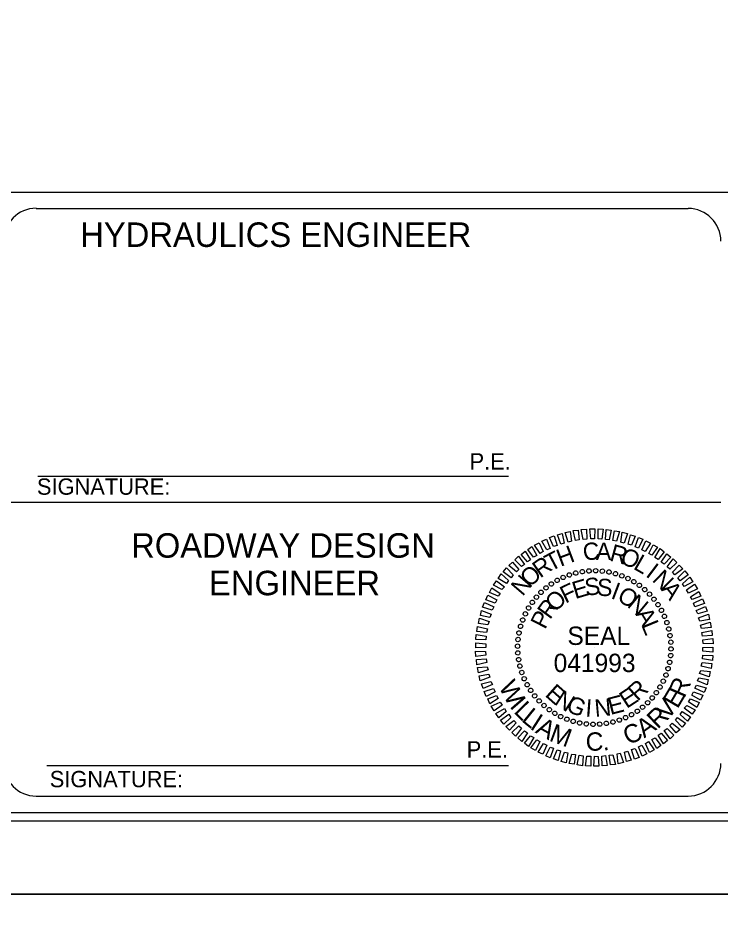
# Model space of a CAD drawing. Extents: x 925297 to 940193, y 663541 to 689899.
# Drawn here: x 935468 to 937191, y 681019 to 683245 of the extents above; entities that cross this region are included whole.
import ezdxf

# ---------------------------------------------------------------- set-up
doc = ezdxf.new("R2010")
doc.units = 0
for name, color, linetype in [('Default', 7, 'Continuous'), ('Sheet Cutting Line CELL', 7, 'Continuous'), ('Sheet Plot Border Inside CELL', 7, 'Continuous'), ('Sheet Plot Border Outside CELL', 7, 'Continuous'), ('Sheet Title CELL', 7, 'Continuous')]:
    doc.layers.add(name, color=color, linetype=linetype)

msp = doc.modelspace()

# ---------------------------------------------------------------- linework, layer by layer
at = {"layer": 'Default'}
for p, q in [((936819.3, 681881.1), (936819.3, 681881.1)), ((936835, 681885.6), (936835, 681885.6)), ((936851.5, 681888.6), (936851.5, 681888.6)), ((936867.6, 681890.9), (936867.6, 681890.9)), ((936884.1, 681891.3), (936884.1, 681891.3)), ((936900.6, 681890.1), (936900.6, 681890.1)), ((936916.8, 681887.5), (936916.8, 681887.5)), ((936932.5, 681884.1), (936932.5, 681884.1)), ((936775.4, 681859), (936775.4, 681859)), ((936789.6, 681867.6), (936789.6, 681867.6)), ((936804.3, 681875.1), (936804.3, 681875.1)), ((936948.3, 681878.9), (936948.3, 681878.9)), ((936963.3, 681872.1), (936963.3, 681872.1)), ((936977.9, 681864.6), (936977.9, 681864.6)), ((936749.9, 681838.4), (936749.9, 681838.4)), ((936762.3, 681849.6), (936762.3, 681849.6)), ((936991.4, 681855.3), (936991.4, 681855.3)), ((937004.5, 681845.1), (937004.5, 681845.1)), ((936728.5, 681813.6), (936728.5, 681813.6)), ((936738.6, 681826.8), (936738.6, 681826.8)), ((937016.1, 681833.9), (937016.1, 681833.9)), ((937027.4, 681821.5), (937027.4, 681821.5)), ((936719.1, 681800.1), (936719.1, 681800.1)), ((937036.8, 681808.4), (937036.8, 681808.4)), ((937045.4, 681794.1), (937045.4, 681794.1)), ((936704.9, 681770.5), (936704.9, 681770.5)), ((936711.6, 681785.5), (936711.6, 681785.5)), ((937052.9, 681779.5), (937052.9, 681779.5)), ((936699.6, 681754.8), (936699.6, 681754.8)), ((937058.9, 681764.5), (937058.9, 681764.5)), ((937063.4, 681748.8), (937063.4, 681748.8)), ((936696.3, 681739), (936696.3, 681739)), ((937066.4, 681732.3), (937066.4, 681732.3)), ((936692.5, 681706.4), (936692.5, 681706.4)), ((936693.6, 681722.9), (936693.6, 681722.9)), ((936880.8, 681703), (936880.8, 681703)), ((937068.6, 681716.1), (937068.6, 681716.1)), ((936692.9, 681689.9), (936692.9, 681689.9)), ((937067.9, 681683.1), (937067.9, 681683.1)), ((937069, 681699.6), (937069, 681699.6)), ((936695.1, 681673.8), (936695.1, 681673.8)), ((936698.1, 681657.3), (936698.1, 681657.3)), ((937065.3, 681667), (937065.3, 681667)), ((936702.6, 681641.5), (936702.6, 681641.5)), ((937056.6, 681635.5), (937056.6, 681635.5)), ((937061.9, 681651.3), (937061.9, 681651.3)), ((936708.6, 681626.5), (936708.6, 681626.5)), ((937049.9, 681620.5), (937049.9, 681620.5)), ((936716.1, 681611.9), (936716.1, 681611.9)), ((936724.8, 681597.6), (936724.8, 681597.6)), ((937033, 681592.4), (937033, 681592.4)), ((937042.4, 681605.9), (937042.4, 681605.9)), ((936734.1, 681584.5), (936734.1, 681584.5)), ((936745.4, 681572.1), (936745.4, 681572.1)), ((937011.6, 681567.6), (937011.6, 681567.6)), ((937022.9, 681579.3), (937022.9, 681579.3)), ((936757, 681560.9), (936757, 681560.9)), ((936770.1, 681550.8), (936770.1, 681550.8)), ((936986.1, 681547), (936986.1, 681547)), ((936999.3, 681556.4), (936999.3, 681556.4)), ((936783.6, 681541.4), (936783.6, 681541.4)), ((936798.3, 681533.9), (936798.3, 681533.9)), ((936813.3, 681527.1), (936813.3, 681527.1)), ((936942.3, 681524.9), (936942.3, 681524.9)), ((936957.3, 681530.9), (936957.3, 681530.9)), ((936971.9, 681538.4), (936971.9, 681538.4)), ((936829, 681521.9), (936829, 681521.9)), ((936844.8, 681518.5), (936844.8, 681518.5)), ((936860.9, 681515.9), (936860.9, 681515.9)), ((936877.4, 681514.8), (936877.4, 681514.8)), ((936893.9, 681515.1), (936893.9, 681515.1)), ((936910, 681517.4), (936910, 681517.4)), ((936926.5, 681520.4), (936926.5, 681520.4))]:
    msp.add_line(p, q, dxfattribs=at)
for points in [[(936835, 681965.5), (936829, 681989.5), (936841.4, 681990.6), (936844, 681966.6)], [(936853, 681967.8), (936848.9, 681991.8), (936861.6, 681993.3), (936862, 681968.9)], [(936871.8, 681969.6), (936869.9, 681994), (936882.3, 681993.6), (936880.8, 681969.3)], [(936889.8, 681969.3), (936889.8, 681993.6), (936902.1, 681993.3), (936898.8, 681968.9)], [(936908.5, 681968.1), (936910, 681992.5), (936922.4, 681990.3), (936917.5, 681966.6)], [(936764.1, 681942.6), (936752.1, 681963.6), (936763.8, 681968.9), (936772.4, 681946)], [(936780.6, 681950.5), (936770.9, 681972.3), (936782.1, 681976.8), (936790, 681952.8)], [(936799, 681956.5), (936790.4, 681979), (936802, 681982.4), (936806.9, 681959.1)], [(936817, 681961.4), (936809.1, 681985), (936821.9, 681987.6), (936824.9, 681963.3)], [(936926.5, 681965.1), (936929.9, 681989.1), (936942.3, 681987.3), (936935.5, 681964)], [(936945.6, 681961), (936949.4, 681985.4), (936962.1, 681982.4), (936953.5, 681959.1)], [(936963.6, 681956.1), (936969.3, 681979.4), (936980.9, 681975.6), (936971.5, 681953.5)], [(936980.5, 681949.4), (936989.1, 681973), (936999.6, 681968.5), (936989.1, 681946.8)], [(936731.5, 681924.3), (936717.6, 681943.4), (936727.4, 681950.5), (936739.8, 681928.8)], [(936748, 681933.6), (936734.1, 681953.9), (936745.8, 681959.9), (936755.1, 681938.1)], [(936997.4, 681942.3), (937006.8, 681964.4), (937018.4, 681959.1), (937005.6, 681938.1)], [(937014.6, 681933.6), (937024.8, 681955), (937036, 681948.6), (937021.8, 681929.1)], [(936702.3, 681901.4), (936685.8, 681917.9), (936694.8, 681926.9), (936709.4, 681906.6)], [(936717.3, 681913), (936701.1, 681931), (936711.3, 681938.9), (936724.4, 681917.9)], [(937029.3, 681923.5), (937042.4, 681945.3), (937052.1, 681937.4), (937037.5, 681919)], [(937044.6, 681912.3), (937058.5, 681932.9), (937068.3, 681924.6), (937051.8, 681907)], [(936689.9, 681888.3), (936670.8, 681903.6), (936680.1, 681912.3), (936695.9, 681894.3)], [(937058.9, 681900.6), (937074.3, 681920.1), (937083.3, 681911.1), (937066, 681895)], [(937072.4, 681887.5), (937088.5, 681905.1), (937097.5, 681896.1), (937078, 681881.5)], [(936665.5, 681859.8), (936645.3, 681872.5), (936652.4, 681883.4), (936670.4, 681866.9)], [(936676.8, 681874), (936657.3, 681888.6), (936665.5, 681898.4), (936682, 681880.8)], [(937085.5, 681874), (937102.8, 681890.9), (937110.6, 681880.8), (937090.8, 681866.5)], [(936654.3, 681844.8), (936633.3, 681856), (936640.8, 681866.5), (936660.3, 681851.5)], [(937096.8, 681859.4), (937115.1, 681875.1), (937122.3, 681864.3), (937101.3, 681852.3)], [(937106.5, 681844), (937126.4, 681858.3), (937133.5, 681847), (937111.8, 681836.5)], [(936645.3, 681828.6), (936623.9, 681838), (936629.5, 681849.6), (936649.8, 681835.8)], [(937116.3, 681827.5), (937137.3, 681840.6), (937142.1, 681829), (937120.8, 681820.4)], [(936630.3, 681794.9), (936607, 681801.6), (936611.9, 681813.3), (936634.4, 681802.8)], [(936637.8, 681811.4), (936614.5, 681820), (936620.1, 681831.6), (936641.5, 681819.6)], [(937123.8, 681811.4), (937145.9, 681822.6), (937150.8, 681810.6), (937127.5, 681803.1)], [(936624.6, 681776.9), (936601.4, 681781.8), (936604, 681794.1), (936627.6, 681784.8)], [(937130.5, 681793.8), (937153.4, 681803.5), (937157.5, 681791.9), (937134.3, 681785.9)], [(936619.8, 681758.9), (936596.5, 681761.9), (936599.1, 681774.6), (936622.8, 681766.8)], [(937136.5, 681775.8), (937160.5, 681784.4), (937162.8, 681772), (937139.1, 681767.9)], [(936616.8, 681739.8), (936592.8, 681742), (936594.3, 681754.8), (936618.6, 681748.8)], [(937141, 681757.8), (937164.6, 681764.9), (937166.9, 681752.1), (937143.3, 681749.9)], [(936614.9, 681721.8), (936590.5, 681722.5), (936591.3, 681734.9), (936615.6, 681730.8)], [(937144.4, 681739.8), (937168.8, 681745), (937169.9, 681732.3), (937145.9, 681730.8)], [(937146.6, 681721.8), (937171, 681724.8), (937171.8, 681712), (937147.4, 681712.8)], [(936614.5, 681703), (936590.1, 681701.9), (936590.1, 681714.6), (936614.5, 681712)], [(937147, 681703), (937171.4, 681704.1), (937171.4, 681691.4), (937147, 681694)], [(936614.9, 681684.3), (936590.5, 681681.3), (936589.8, 681694), (936614.1, 681693.3)], [(937146.6, 681684.3), (937171, 681683.5), (937170.3, 681671.1), (937145.9, 681675.3)], [(936617.1, 681666.3), (936592.8, 681661), (936591.6, 681673.8), (936615.6, 681675.3)], [(937144.8, 681666.3), (937168.8, 681664), (937167.3, 681651.3), (937142.9, 681657.3)], [(936620.5, 681648.3), (936596.9, 681641.1), (936594.6, 681653.9), (936618.3, 681656.1)], [(936625, 681630.3), (936601, 681621.6), (936598.8, 681634), (936622.4, 681638.1)], [(937141.8, 681647.1), (937165, 681644.1), (937162.4, 681631.4), (937138.8, 681639.3)], [(936631, 681612.3), (936608.1, 681602.5), (936604, 681614.1), (936627.3, 681620.1)], [(937136.9, 681629.1), (937160.1, 681624.3), (937157.5, 681611.9), (937133.9, 681621.3)], [(936637.8, 681594.6), (936615.6, 681583.4), (936610.8, 681595.4), (936634, 681602.9)], [(937123.8, 681594.6), (937147, 681586), (937141.4, 681574.4), (937120, 681586.4)], [(937131.3, 681611.1), (937154.5, 681604.4), (937149.6, 681592.8), (937127.1, 681603.3)], [(936645.3, 681578.5), (936624.3, 681565.4), (936619.4, 681577), (936640.8, 681585.6)], [(936655, 681562), (936635.1, 681547.8), (936628, 681559), (936649.8, 681569.5)], [(937116.3, 681577.4), (937137.6, 681568), (937132, 681556.4), (937111.8, 681570.3)], [(936664.8, 681546.6), (936646.4, 681530.9), (936639.3, 681541.8), (936660.3, 681553.8)], [(937096, 681546.3), (937116.3, 681533.5), (937109.1, 681522.6), (937091.1, 681539.1)], [(937107.3, 681561.3), (937128.3, 681550), (937120.8, 681539.5), (937101.3, 681554.5)], [(936676, 681532), (936658.8, 681515.1), (936650.9, 681525.3), (936670.8, 681539.5)], [(936689.1, 681518.5), (936673, 681500.9), (936664, 681509.9), (936683.5, 681524.5)], [(937084.8, 681532), (937104.3, 681517.4), (937096, 681507.6), (937079.5, 681525.3)], [(936702.6, 681505.4), (936687.3, 681485.9), (936678.3, 681494.9), (936695.5, 681511)], [(937059.3, 681504.6), (937075.8, 681488.1), (937066.8, 681479.1), (937052.1, 681499.4)], [(937071.6, 681517.8), (937090.8, 681502.4), (937081.4, 681493.8), (937065.6, 681511.8)], [(936716.9, 681493.8), (936703, 681473.1), (936693.3, 681481.4), (936709.8, 681499)], [(936732.3, 681482.5), (936719.1, 681460.8), (936709.4, 681468.6), (936724, 681487)], [(937030, 681481.8), (937043.9, 681462.6), (937034.1, 681455.5), (937021.8, 681477.3)], [(937044.3, 681493), (937060.4, 681475), (937050.3, 681467.1), (937037.1, 681488.1)], [(936746.9, 681472.4), (936736.8, 681451), (936725.5, 681457.4), (936739.8, 681476.9)], [(936764.1, 681463.8), (936754.8, 681441.6), (936743.1, 681446.9), (936755.9, 681467.9)], [(936781, 681456.6), (936772.4, 681433), (936761.9, 681437.5), (936772.4, 681459.3)], [(936997.4, 681463.4), (937009.4, 681442.4), (936997.8, 681437.1), (936989.1, 681460)], [(937013.5, 681472.4), (937027.4, 681452.1), (937015.8, 681446.1), (937006.4, 681467.9)], [(936797.9, 681449.9), (936792.3, 681426.6), (936780.6, 681430.4), (936790, 681452.5)], [(936815.9, 681445), (936812.1, 681420.6), (936799.4, 681423.6), (936808, 681446.9)], [(936835, 681440.9), (936831.6, 681416.9), (936819.3, 681418.8), (936826, 681442)], [(936853, 681437.9), (936851.5, 681413.5), (936839.1, 681415.8), (936844, 681439.4)], [(936871.8, 681436.8), (936871.8, 681412.4), (936859.4, 681412.8), (936862.8, 681437.1)], [(936889.8, 681436.4), (936891.6, 681412), (936879.3, 681412.4), (936880.8, 681436.8)], [(936908.5, 681438.3), (936912.6, 681414.3), (936899.9, 681412.8), (936899.5, 681437.1)], [(936926.5, 681440.5), (936932.5, 681416.5), (936920.1, 681415.4), (936917.5, 681439.4)], [(936944.5, 681444.6), (936952.4, 681421), (936939.6, 681418.4), (936936.6, 681442.8)], [(936962.5, 681449.5), (936971.1, 681427), (936959.5, 681423.6), (936954.6, 681446.9)], [(936980.9, 681455.5), (936990.6, 681433.8), (936979.4, 681429.3), (936971.5, 681453.3)]]:
    msp.add_lwpolyline(points, close=True, dxfattribs=at)
for centre, major_axis in [((936804.3, 681874.8), (-2.2, 4.93)), ((936819.5, 681880.9), (-1.76, 5.11)), ((936835.3, 681885.5), (-1.31, 5.24)), ((936851.3, 681888.8), (-0.84, 5.33)), ((936867.6, 681890.7), (-0.38, 5.39)), ((936884, 681891.1), (0.09, 5.4)), ((936900.4, 681890.1), (0.56, 5.37)), ((936916.7, 681887.7), (1.03, 5.3)), ((936932.6, 681883.8), (1.49, 5.19)), ((936948.2, 681878.6), (1.94, 5.04)), ((936775.6, 681859), (-3.02, 4.48)), ((936789.6, 681867.5), (-2.62, 4.72)), ((936963.2, 681872.1), (2.37, 4.85)), ((936977.6, 681864.2), (2.78, 4.63)), ((936991.3, 681855.2), (3.17, 4.37)), ((936750.1, 681838.3), (-3.75, 3.88)), ((936762.4, 681849.2), (-3.4, 4.2)), ((937004.2, 681845), (3.54, 4.08)), ((937016.1, 681833.7), (3.88, 3.75)), ((936728.6, 681813.6), (-4.37, 3.17)), ((936738.8, 681826.4), (-4.08, 3.54)), ((937026.9, 681821.4), (4.2, 3.4)), ((937036.7, 681808.2), (4.48, 3.02)), ((936711.7, 681785.5), (-4.85, 2.37)), ((936719.5, 681799.9), (-4.63, 2.78)), ((937045.3, 681794.2), (4.72, 2.62)), ((936705.2, 681770.4), (-5.04, 1.94)), ((937052.6, 681779.5), (4.93, 2.2)), ((937058.6, 681764.2), (5.11, 1.76)), ((936699.9, 681754.9), (-5.19, 1.49)), ((937063.3, 681748.5), (5.24, 1.31)), ((936693.7, 681722.7), (-5.37, 0.56)), ((936696.1, 681738.9), (-5.3, 1.03)), ((937066.5, 681732.4), (5.33, 0.84)), ((936692.7, 681706.3), (-5.4, 0.09)), ((937068.4, 681716.1), (5.39, 0.38)), ((937068.8, 681699.7), (5.4, -0.09)), ((936693.1, 681689.9), (-5.39, -0.38)), ((936695, 681673.6), (-5.33, -0.84)), ((937067.8, 681683.3), (5.37, -0.56)), ((936698.2, 681657.5), (-5.24, -1.31)), ((937061.6, 681651.2), (5.19, -1.49)), ((937065.4, 681667.1), (5.3, -1.03)), ((936702.9, 681641.8), (-5.11, -1.76)), ((937056.4, 681635.6), (5.04, -1.94)), ((936708.9, 681626.5), (-4.93, -2.2)), ((936716.2, 681611.8), (-4.72, -2.62)), ((937042, 681606.1), (4.63, -2.78)), ((937049.8, 681620.6), (4.85, -2.37)), ((936724.8, 681597.8), (-4.48, -3.02)), ((936734.6, 681584.6), (-4.2, -3.4)), ((937032.9, 681592.4), (4.37, -3.17)), ((936745.5, 681572.3), (-3.88, -3.75)), ((937011.4, 681567.7), (3.75, -3.88)), ((937022.7, 681579.6), (4.08, -3.54)), ((936757.4, 681561), (-3.54, -4.08)), ((936770.2, 681550.8), (-3.17, -4.37)), ((936783.9, 681541.8), (-2.78, -4.63)), ((936985.9, 681547.1), (3.02, -4.48)), ((936999.1, 681556.8), (3.4, -4.2)), ((936798.3, 681533.9), (-2.37, -4.85)), ((936813.4, 681527.4), (-1.94, -5.04)), ((936828.9, 681522.2), (-1.49, -5.19)), ((936844.9, 681518.4), (-1.03, -5.3)), ((936910.2, 681517.2), (0.84, -5.33)), ((936926.3, 681520.5), (1.31, -5.24)), ((936942, 681525.2), (1.76, -5.11)), ((936957.3, 681531.2), (2.2, -4.93)), ((936972, 681538.5), (2.62, -4.72)), ((936861.1, 681515.9), (-0.56, -5.37)), ((936877.5, 681514.9), (-0.09, -5.4)), ((936893.9, 681515.4), (0.38, -5.39))]:
    msp.add_ellipse(centre, major_axis=major_axis, ratio=0.999708, dxfattribs=at)
at = {"layer": 'Sheet Cutting Line CELL'}
msp.add_line((925296.7, 681098.7), (938768.7, 681098.7), dxfattribs=at)
at = {"layer": 'Sheet Plot Border Inside CELL'}
msp.add_lwpolyline([(925400.7, 681278.2), (938732.7, 681278.2), (938732.7, 689719), (925400.7, 689719)], close=True, dxfattribs=at)
at = {"layer": 'Sheet Plot Border Outside CELL'}
for points in [[(938768.7, 689898.6), (925296.7, 689898.6), (925296.7, 681098.7), (938768.7, 681098.7)], [(925296.7, 672338.7), (938764.7, 672338.7), (938764.7, 681098.7), (925296.7, 681098.7)]]:
    msp.add_lwpolyline(points, close=True, dxfattribs=at)
at = {"layer": 'Sheet Title CELL'}
for p, q in [((927152.7, 682818.7), (938512.7, 682818.7)), ((935512.7, 682778.7), (937110.9, 682778.7)), ((935516.7, 682122.8), (936670.7, 682122.8)), ((935425.5, 682058.9), (937190.9, 682058.9)), ((935538.7, 681414.3), (936670.7, 681414.2))]:
    msp.add_line(p, q, dxfattribs=at)
for points in [[(935512.7, 681338.7), (937110.9, 681338.7)], [(926712.7, 681298.6), (938552.7, 681298.6)]]:
    msp.add_lwpolyline(points, dxfattribs=at)
for centre, start, end in [((935512.7, 682699.1), 90, 180), ((937110.9, 682698.7), 0, 90), ((935512.7, 681419.1), 180, 270), ((937110.9, 681419.2), 270, 360)]:
    msp.add_arc(centre, 80, start, end, dxfattribs=at)

# ---------------------------------------------------------------- texts
at = {"layer": 'Default'}
for s, height, rotation, p in [('H', 42.3, 20.6195, (936797.9, 681900.6)), ('C', 42.3, 6.2199, (936854.9, 681915.6)), ('A', 42.3, 359.0203, (936884.5, 681917.9)), ('R', 42.3, 344.6211, (936916, 681916.4)), ('T', 42.3, 27.8198, (936773.5, 681888.3)), ('O', 42.3, 337.4212, (936941.1, 681910.8)), ('L', 42.3, 330.2209, (936974.1, 681896.9)), ('R', 42.3, 35.0205, (936748, 681871.8)), ('I', 42.3, 323.0201, (937004.5, 681878.9)), ('N', 42.3, 49.4235, (936704.9, 681826.8)), ('O', 42.3, 42.2217, (936722.1, 681848.5)), ('N', 42.3, 315.8189, (937020.6, 681867.3)), ('F', 42.3, 25.967, (936809.9, 681810.3)), ('E', 42.3, 16.6111, (936833.9, 681821.5)), ('S', 42.3, 7.2556, (936859.8, 681829.4)), ('S', 42.3, 357.9004, (936886.8, 681829.8)), ('I', 42.3, 339.1896, (936919, 681824.5)), ('A', 42.3, 308.6172, (937042.8, 681845.1)), ('O', 42.3, 44.6812, (936785.1, 681788.1)), ('O', 42.3, 329.8335, (936934, 681819.3)), ('R', 42.3, 54.0397, (936772, 681769.8)), ('N', 42.3, 320.4766, (936959.1, 681804.3)), ('P', 42.3, 63.3989, (936760, 681745.8)), ('A', 42.3, 301.7603, (936980.5, 681784.8)), ('L', 42.3, 292.4008, (936995.1, 681758.9)), ('SEAL', 44.99, 360, (936814.8, 681709.4)), ('W', 45, 298.3574, (936645.2, 681607.3)), ('E', 42.3, 318.2769, (936757.8, 681585.6)), ('R', 42.3, 42.4814, (936986.5, 681569.9)), ('R', 45, 66.6964, (937102, 681577.6)), ('N', 42.3, 327.634, (936780.3, 681565.4)), ('E', 42.3, 33.1241, (936959.9, 681552.3)), ('E', 45, 59.5871, (937084.7, 681551.2)), ('I', 45, 310.8915, (936671.6, 681558.4)), ('L', 45, 314.6934, (936681.6, 681544.9)), ('G', 42.3, 336.9902, (936808.8, 681548.5)), ('I', 42.3, 355.7012, (936857.9, 681534.3)), ('N', 42.3, 5.0564, (936883, 681533.1)), ('E', 42.3, 14.4118, (936920.1, 681537.6)), ('V', 45, 51.3341, (937060.8, 681523.5)), ('L', 45, 320.9682, (936700.1, 681524.1)), ('R', 45, 43.8538, (937035.9, 681501.6)), ('I', 45, 327.2429, (936720.8, 681505.4)), ('A', 45, 331.0449, (936734.2, 681495.2)), ('A', 45, 35.0135, (937003.1, 681480.1)), ('M', 45, 339.8852, (936767.9, 681475.2)), ('C', 45, 25.4313, (936964.3, 681462.9)), ('C', 45, 1.6151, (936860.2, 681449.6)), ('.', 45, 11.1972, (936902.7, 681449.7))]:
    msp.add_text(s, height=height, rotation=rotation, dxfattribs=at).set_placement(p)
msp.add_text('041993', height=44.99, dxfattribs=at).set_placement((936781, 681642.9))
at = {"layer": 'Sheet Title CELL'}
for s, height, p in [(' HYDRAULICS ENGINEER', 60, (935598.3, 682684.6)), ('P.E.', 40, (936575, 682139.2)), ('SIGNATURE:', 40, (935514.5, 682077.3)), ('ROADWAY DESIGN', 59.995, (935745.5, 681923.1)), ('ENGINEER', 60, (935936.3, 681831.1)), ('P.E.', 40, (936567.9, 681433.5)), ('SIGNATURE:', 40, (935545.9, 681360.7))]:
    msp.add_text(s, height=height, rotation=360, dxfattribs=at).set_placement(p)

doc.saveas('drawing.dxf')
